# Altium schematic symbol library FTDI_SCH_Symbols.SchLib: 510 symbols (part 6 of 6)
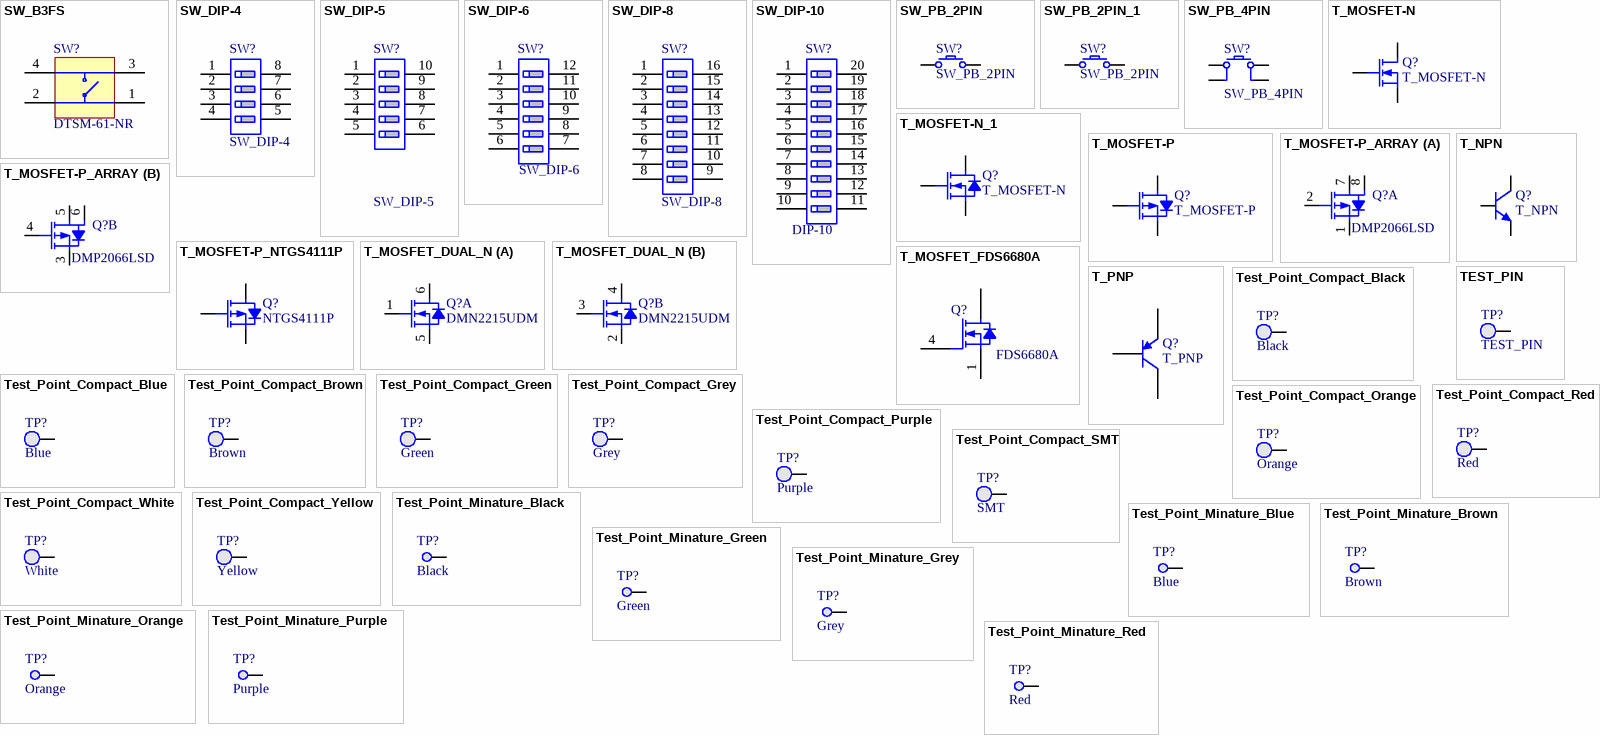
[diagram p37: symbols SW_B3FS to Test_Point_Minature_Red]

## Test_Point_Minature_Purple
designator TP?, comment Purple
Test Point; PTH; Minature; Purple; Keystone; 5119; Manufacturer: Keystone Electronics; ManufacturerPartNo: 5119; Note: TEST POINT PC MINI T/H PURPLE
footprint TEST_PIN_MULTILAYER (Test pin; 0.8mm / 1.6mm, multilayer)
pins: TP

## Test_Point_Minature_Red
designator TP?, comment Red
Test Point; PTH; Minature; Red; Keystone; 5000; Manufacturer: Keystone Electronics; ManufacturerPartNo: 5000; Note: TEST POINT PC MINI .040"D RED
footprint TEST_PIN_MULTILAYER (Test pin; 0.8mm / 1.6mm, multilayer)
pins: TP

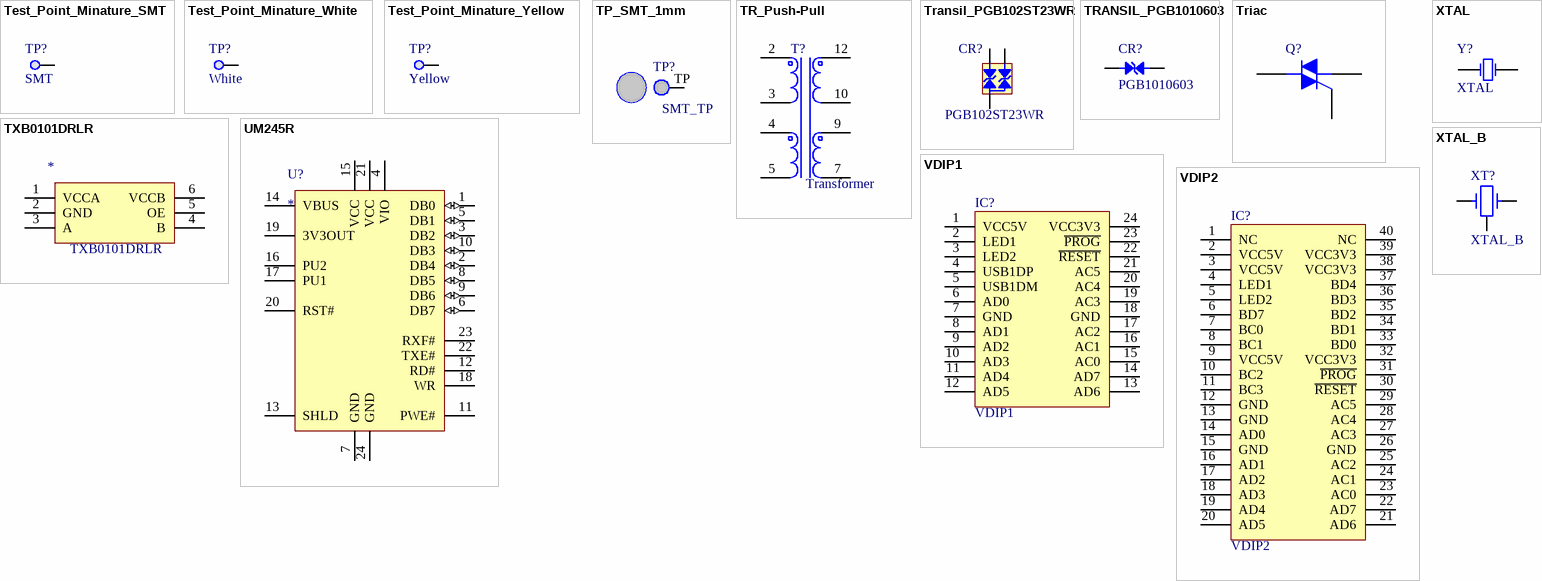
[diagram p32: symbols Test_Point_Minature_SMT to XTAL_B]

## Test_Point_Minature_SMT
designator TP?, comment SMT
Test Point; SMT; Minature; Keystone; 5015; Manufacturer: Keystone Electronics; ManufacturerPartNo: 5015; Note: PC TEST POINT MINIATURE SMT
footprint TEST_PIN_MULTILAYER (Test pin; 0.8mm / 1.6mm, multilayer)
pins: TP

## Test_Point_Minature_White
designator TP?, comment White
Test Point; PTH; Minature; White; Keystone; 5002; Manufacturer: Keystone Electronics; ManufacturerPartNo: 5002; Note: TEST POINT PC MINI .040"D WHITE
footprint TEST_PIN_MULTILAYER (Test pin; 0.8mm / 1.6mm, multilayer)
pins: TP

## Test_Point_Minature_Yellow
designator TP?, comment Yellow
Test Point; PTH; Minature; Yellow; Keystone; 5004; Manufacturer: Keystone Electronics; ManufacturerPartNo: 5004; Note: TEST POINT PC MINI .040"D YELLOW
footprint TEST_PIN_MULTILAYER (Test pin; 0.8mm / 1.6mm, multilayer)
pins: TP

## TP_SMT_1mm
designator TP?, comment SMT_TP
footprint Model Name (Footprint not found)
footprint TP_SMT_1MM
pins: TP

## TR_Push-Pull
designator T?, comment Transformer
TR_Push-Pull
footprint IND-C2012-0805 (Chip Inductor; Body 2 x 1.2 mm (LxW typ))
pins: 1 hidden, 2, 3, 4, 5, 6 hidden, 7, 8 hidden, 9, 10, 11 hidden, 12

## Transil_PGB102ST23WR
designator CR?, comment PGB102ST23WR
Transil; Littlefuse; SOT-23
footprint SOT23-3AL (SOT23 SMT Package)
pins: 1, 2, 3

## TRANSIL_PGB1010603
designator CR?, comment PGB1010603
ESD suppressor (transil)
simulation model ZENER (Diode)
signal-integrity model D Zener
footprint PGB1010603 (Chip Transil, Littelfuse, PGB1 series, 2-Leads, Body 1.6x0.8mm, IPC Medium Density)
pins: 1, 2

## Triac
designator Q?
Silicon Bidirectional Triode Thyristor; Note: Pin 2 is electrically connected to Pin 4 (TAB)
footprint 369-03 (TO, Thru-Hole, Vertical, Heatsink Mounted; 3 In-Line Leads; Pitch 2.28 mm)
simulation model MAC15A8 (Spice Subcircuit)
pins: 1 M1, 2 M2, 3 G

## TXB0101DRLR
designator *
1-BIT BIDIRECTIONAL VOLTAGE-LEVEL TRANSLATOR  FOR OPEN-DRAIN AND PUSH-PULL APPLICATIONS
footprint QFN50P120X160X75-6N (QFN, 6-Leads, Body 1.7x1.3mm (max), Pitch 0.50mm, IPC Medium Density)
pins: 1 VCCA, 2 GND, 3 A, 4 B, 5 OE, 6 VCCB

## UM245R
designator U?
UM245R; FT245R DIP Module; FTDI
pins: 1 DB0 (io), 2 DB4 (io), 3 DB2 (io), 4 VIO, 5 DB1 (io), 6 DB7 (io), 7 GND (power), 8 DB5 (io), 9 DB6 (io), 10 DB3 (io), 11 PWE#, 12 RD#, 13 SHLD, 14 VBUS, 15 VCC, 16 PU2, 17 PU1, 18 WR, 19 3V3OUT (power), 20 RST#, 21 VCC, 22 TXE#, 23 RXF#, 24 GND (power)

## VDIP1
designator IC?
FTDI VDIP1 module
pins: 1 VCC5V, 2 LED1, 3 LED2, 4 USB1DP, 5 USB1DM, 6 AD0, 7 GND, 8 AD1, 9 AD2, 10 AD3, 11 AD4, 12 AD5, 13 AD6, 14 AD7, 15 AC0, 16 AC1, 17 AC2, 18 GND, 19 AC3, 20 AC4, 21 AC5, 22 ~{RESET}, 23 ~{PROG}, 24 VCC3V3

## VDIP2
designator IC?
FTDI VDIP2 module
footprint ZIF-40 (40 pin ZIF socket)
pins: 1 NC, 2 VCC5V, 3 VCC5V, 4 LED1, 5 LED2, 6 BD7, 7 BC0, 8 BC1, 9 VCC5V, 10 BC2, 11 BC3, 12 GND, 13 GND, 14 AD0, 15 GND, 16 AD1, 17 AD2, 18 AD3, 19 AD4, 20 AD5, 21 AD6, 22 AD7, 23 AC0, 24 AC1, 25 AC2, 26 GND, 27 AC3, 28 AC4, 29 AC5, 30 ~{RESET}, 31 ~{PROG}, 32 VCC3V3, 33 BD0, 34 BD1, 35 BD2, 36 BD3, 37 BD4, 38 VCC3V3, 39 VCC3V3, 40 NC

## XTAL
designator Y?
Crystal Oscillator
simulation model XTAL (Spice Subcircuit)
footprint XTAL1B
footprint Crystal_F9_eCera (F9 series, Glass Sealed Quartz Crystal; eCera; 5x3.2mm)
footprint Crystal_G3_eCera (Tuning Fork Quartz Crystal; 32.768kHz; SMD)
pins: 1 OSC1, 2 OSC2

## XTAL_B
designator XT?
footprint CRYSTAL_HC49_3Pin (Crystal with ground pin)
pins: 1, 2, 3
